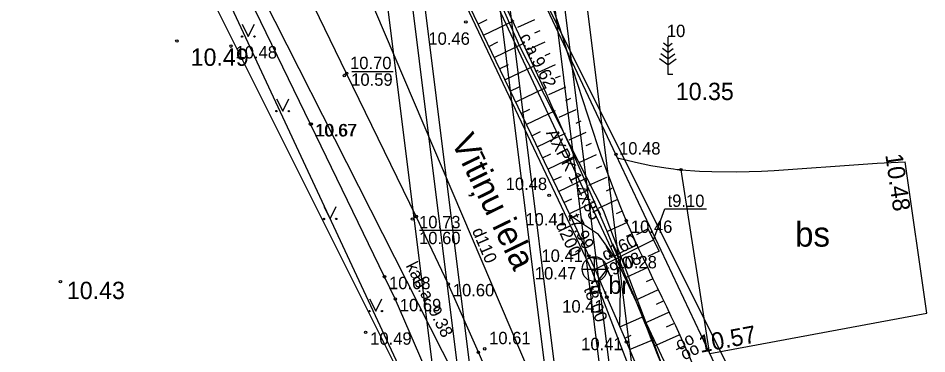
# Model space of a CAD drawing. Extents: x 502312.8 to 502402.4, y 308528.5 to 308602.
# Drawn here: x 502364.65 to 502401.34, y 308553.83 to 308567.38 of the extents above; entities that cross this region are included whole.
import ezdxf

# ---------------------------------------------------------------- set-up
doc = ezdxf.new("R2010")
doc.units = 0
for name, color, linetype in [('24', 7, 'Continuous'), ('APGR_SARK_####_####_#', 7, 'Continuous'), ('APGS_ACRL_####_####_#', 7, 'Continuous'), ('APGS_ACRL_####_TKST_#', 7, 'Continuous'), ('APGS_VADP_ZSPR_####_I', 7, 'Continuous'), ('APGS_VADP_ZSPR_TKST_I', 7, 'Continuous'), ('CELI_CAPM_####_####_#', 7, 'Continuous'), ('CELI_CMAL_####_####_#', 7, 'Continuous'), ('CELI_CSEG_####_TKST_#', 7, 'Continuous'), ('CELI_IELA_####_TKST_#', 7, 'Continuous'), ('ELEK_VADP_ZSPR_####_#', 7, 'Continuous'), ('ELEK_VADP_ZSPR_TKST_#', 7, 'Continuous'), ('ELEK_VADV_ASP1_####_#', 7, 'Continuous'), ('Level 51-1', 7, 'Continuous'), ('NORB_ZOGS_ZSTP_####_#', 7, 'Continuous'), ('RELJ_AATZ_####_TKST_#', 7, 'Continuous'), ('RELJ_ELEM_####_####_#', 7, 'Continuous'), ('RELJ_NOGA_####_####_#', 7, 'Continuous'), ('RELJ_NOGL_####_####_#', 7, 'Continuous'), ('SAKK_IZVK_####_TKST_#', 7, 'Continuous'), ('SAKK_KKAN_####_####_#', 7, 'Continuous'), ('SKAN_ELEM_####_####_#', 7, 'Continuous'), ('SKAN_ELEM_PAST_TKST_#', 7, 'Continuous'), ('SKAN_VADP_PAST_####_I', 7, 'Continuous'), ('SKAN_VADP_PAST_TKST_I', 7, 'Continuous'), ('TERT_DIAM_####_TKST_#', 7, 'Continuous'), ('TERT_ELEM_####_####_#', 7, 'Continuous'), ('TERT_KONT_####_####_#', 7, 'Continuous'), ('UDTK_VADP_UDEN_####_#', 7, 'Continuous'), ('UDTK_VADP_UDEN_TKST_#', 7, 'Continuous')]:
    doc.layers.add(name, color=color, linetype=linetype)

msp = doc.modelspace()

# ---------------------------------------------------------------- linework, layer by layer
at = {"layer": '24'}
for p, q in [((502364.984, 308585.593), (502381.693, 308549.732)), ((502394.734, 308550.484), (502382.191, 308575.562))]:
    msp.add_line(p, q, dxfattribs=at)
at = {"layer": 'APGR_SARK_####_####_#'}
for p, q in [((502382.191, 308575.562), (502394.734, 308550.484)), ((502369.848, 308573.413), (502381.693, 308549.732))]:
    msp.add_line(p, q, dxfattribs=at)
at = {"layer": 'APGS_ACRL_####_####_#'}
msp.add_lwpolyline([(502372.273, 308571.554), (502372.68, 308571.725), (502380.284, 308575.836), (502380.655, 308575.903), (502380.972, 308575.586), (502382.116, 308572.55), (502384.894, 308566.257), (502388.272, 308559.63), (502390.397, 308554.024), (502392.869, 308547.38), (502392.92, 308547.155)], dxfattribs=at)
at = {"layer": 'APGS_VADP_ZSPR_####_I'}
msp.add_lwpolyline([(502372.273, 308571.554), (502372.68, 308571.725), (502380.284, 308575.836), (502380.655, 308575.903), (502380.972, 308575.586), (502382.116, 308572.55), (502384.894, 308566.257), (502388.272, 308559.63), (502390.397, 308554.024), (502392.869, 308547.38), (502392.92, 308547.155)], dxfattribs=at)
at = {"layer": 'CELI_CAPM_####_####_#'}
for points in [[(502378.409, 308577.074), (502378.645, 308576.556), (502381.101, 308571.495), (502383.047, 308567.49), (502386.95, 308559.382), (502387.372, 308558.481), (502387.692, 308557.774), (502387.933, 308557.255), (502388.418, 308556.115), (502389.212, 308554.306), (502389.599, 308553.373), (502390.383, 308551.504), (502391.144, 308549.652), (502391.872, 308547.788), (502392.589, 308545.929), (502393.393, 308543.693), (502393.705, 308542.827)], [(502392.53, 308528.536), (502392.273, 308529.412), (502391.34, 308532.322), (502390.324, 308535.341), (502389.269, 308538.416), (502388.272, 308541.254), (502387.358, 308543.683), (502386.314, 308546.51), (502385.198, 308549.256), (502384.849, 308550.113), (502383.229, 308553.89), (502382.013, 308556.65), (502380.717, 308559.374), (502377.909, 308565.152), (502373.303, 308574.647)]]:
    msp.add_lwpolyline(points, dxfattribs=at)
at = {"layer": 'CELI_CMAL_####_####_#'}
for points in [[(502390.232, 308528.536), (502388.865, 308532.737), (502388.043, 308535.197), (502387.28, 308537.476), (502386.263, 308540.301), (502385.235, 308543.076), (502384.524, 308544.988), (502383.511, 308547.559), (502382.468, 308550.05), (502379.873, 308556.046), (502379.438, 308556.939), (502376.448, 308563.104), (502371.317, 308573.674)], [(502388.853, 308561.737), (502389.58, 308561.564), (502390.189, 308561.437), (502390.8, 308561.334), (502391.107, 308561.293), (502391.26, 308561.276), (502391.337, 308561.268), (502391.414, 308561.261), (502392.163, 308561.209), (502392.663, 308561.189), (502393.663, 308561.183), (502394.669, 308561.21), (502395.173, 308561.233), (502395.927, 308561.279), (502398.198, 308561.445), (502399.333, 308561.522), (502400.465, 308561.577)], [(502401.338, 308555.467), (502400.465, 308561.577)], [(502392.559, 308553.884), (502391.414, 308561.261)], [(502388.946, 308554.913), (502388.966, 308556.489), (502388.783, 308557.67), (502388.074, 308558.645), (502386.943, 308559.396)], [(502387.714, 308557.727), (502388.247, 308557.635), (502388.387, 308557.209), (502388.11, 308556.838)], [(502392.582, 308553.835), (502401.338, 308555.467)]]:
    msp.add_lwpolyline(points, dxfattribs=at)
at = {"layer": 'ELEK_VADP_ZSPR_####_#'}
msp.add_line((502372.196, 308572.819), (502383.39, 308550.751), dxfattribs=at)
at = {"layer": 'ELEK_VADV_ASP1_####_#'}
msp.add_line((502392.53, 308528.536), (502385.08, 308588.302), dxfattribs=at)
for points in [[(502389.003, 308528.536), (502381.58, 308588.091)], [(502389.406, 308528.536), (502381.98, 308588.115)], [(502391.22, 308528.536), (502383.78, 308588.224)], [(502391.623, 308528.536), (502384.18, 308588.248)], [(502384.469, 308528.536), (502377.051, 308588.051)], [(502385.476, 308528.536), (502378.08, 308587.88)], [(502385.98, 308528.536), (502378.58, 308587.91)]]:
    msp.add_lwpolyline(points, dxfattribs=at)
at = {"layer": 'Level 51-1'}
msp.add_line((502364.984, 308585.593), (502381.693, 308549.732), dxfattribs=at)
at = {"layer": 'NORB_ZOGS_ZSTP_####_#'}
msp.add_line((502388.785, 308561.881), (502380.198, 308580.055), dxfattribs=at)
msp.add_lwpolyline([(502394.21, 308550.464), (502393.13, 308552.674), (502388.785, 308561.881)], dxfattribs=at)
at = {"layer": 'RELJ_AATZ_####_TKST_#'}
for p, q in [((502378.121, 308565.226), (502379.789, 308565.226)), ((502380.859, 308558.821), (502382.526, 308558.821))]:
    msp.add_line(p, q, dxfattribs=at)
at = {"layer": 'RELJ_ELEM_####_####_#'}
for centre in [(502382.724, 308567.227), (502371.056, 308566.457), (502373.239, 308566.253), (502377.816, 308565.064), (502377.909, 308565.152), (502376.448, 308563.104), (502376.479, 308563.11), (502388.785, 308561.881), (502391.414, 308561.261), (502386.088, 308560.227), (502386.95, 308559.382), (502380.565, 308559.269), (502380.717, 308559.374), (502389.203, 308559.21), (502387.372, 308558.481), (502387.692, 308557.774), (502388.579, 308557.78), (502379.438, 308556.939), (502366.353, 308556.739), (502382.013, 308556.65), (502388.418, 308556.115), (502379.873, 308556.046), (502378.676, 308554.696), (502389.212, 308554.306), (502383.229, 308553.89), (502383.485, 308554.029)]:
    msp.add_circle(centre, 0.05, dxfattribs=at)
at = {"layer": 'RELJ_NOGA_####_####_#'}
for p, q in [((502383.214, 308567.143), (502383.587, 308567.322)), ((502383.431, 308566.692), (502384.67, 308567.289)), ((502385.499, 308567.32), (502384.804, 308567.003)), ((502385.706, 308566.865), (502385.499, 308566.771)), ((502383.648, 308566.242), (502384.018, 308566.42)), ((502385.914, 308566.41), (502385.228, 308566.097)), ((502383.865, 308565.791), (502385.095, 308566.383)), ((502386.121, 308565.955), (502385.916, 308565.862)), ((502384.082, 308565.341), (502384.449, 308565.517)), ((502384.299, 308564.89), (502385.516, 308565.476)), ((502386.329, 308565.501), (502385.648, 308565.19)), ((502386.537, 308565.046), (502386.332, 308564.953)), ((502384.515, 308564.44), (502384.878, 308564.614)), ((502386.744, 308564.591), (502386.063, 308564.28)), ((502384.732, 308563.989), (502385.933, 308564.567)), ((502386.952, 308564.136), (502386.747, 308564.043)), ((502384.949, 308563.538), (502385.306, 308563.71)), ((502385.166, 308563.088), (502386.346, 308563.656)), ((502387.159, 308563.681), (502386.475, 308563.369)), ((502387.367, 308563.226), (502387.16, 308563.132)), ((502385.383, 308562.637), (502385.733, 308562.806)), ((502385.6, 308562.187), (502386.754, 308562.743)), ((502387.574, 308562.771), (502386.881, 308562.455)), ((502387.782, 308562.317), (502387.572, 308562.221)), ((502385.817, 308561.736), (502386.159, 308561.901)), ((502386.034, 308561.286), (502387.157, 308561.827)), ((502387.99, 308561.862), (502387.282, 308561.538)), ((502388.198, 308561.407), (502387.983, 308561.309)), ((502386.25, 308560.835), (502386.582, 308560.995)), ((502386.467, 308560.385), (502387.554, 308560.908)), ((502388.406, 308560.952), (502387.678, 308560.619)), ((502388.614, 308560.498), (502388.391, 308560.396)), ((502386.684, 308559.934), (502387.004, 308560.088)), ((502386.901, 308559.484), (502387.945, 308559.986)), ((502388.822, 308560.043), (502388.066, 308559.697)), ((502389.03, 308559.588), (502388.798, 308559.482)), ((502389.238, 308559.134), (502388.448, 308558.772)), ((502389.446, 308558.679), (502389.203, 308558.568)), ((502389.655, 308558.225), (502388.822, 308557.843)), ((502389.863, 308557.77), (502389.606, 308557.652)), ((502390.071, 308557.316), (502389.192, 308556.912)), ((502390.28, 308556.861), (502390.009, 308556.737)), ((502390.488, 308556.406), (502389.561, 308555.981)), ((502390.696, 308555.952), (502390.411, 308555.821)), ((502390.905, 308555.497), (502389.93, 308555.05)), ((502388.942, 308554.92), (502389.827, 308555.309)), ((502391.113, 308555.043), (502390.813, 308554.906)), ((502389.143, 308554.462), (502389.404, 308554.577)), ((502389.338, 308554.002), (502390.203, 308554.361)), ((502391.321, 308554.588), (502390.299, 308554.12)), ((502391.53, 308554.134), (502391.216, 308553.99))]:
    msp.add_line(p, q, dxfattribs=at)
msp.add_spline([(502392.938, 308547.462), (502392.327, 308552.238), (502392.05, 308552.998), (502389.203, 308559.21), (502380.766, 308577.667), (502379.858, 308578.409), (502378.565, 308579.008)], degree=3, dxfattribs=at)
at = {"layer": 'RELJ_NOGL_####_####_#'}
msp.add_spline([(502392.938, 308547.462), (502388.885, 308557.685), (502380.794, 308575.385), (502379.35, 308578.02), (502378.565, 308579.008)], degree=3, dxfattribs=at)
at = {"layer": 'SAKK_KKAN_####_####_#'}
msp.add_lwpolyline([(502378.865, 308578.852), (502390.92, 308553.118), (502393.046, 308548.902)], dxfattribs=at)
at = {"layer": 'SKAN_ELEM_####_####_#'}
for p, q in [((502387.921, 308556.749), (502387.921, 308557.749)), ((502387.421, 308557.249), (502388.421, 308557.249))]:
    msp.add_line(p, q, dxfattribs=at)
msp.add_lwpolyline([(502389.629, 308558.65), (502390.076, 308558.874), (502390.524, 308557.98), (502390.077, 308557.756)], dxfattribs=at)
msp.add_circle((502387.921, 308557.249), 0.5, dxfattribs=at)
at = {"layer": 'SKAN_VADP_PAST_####_I'}
for points in [[(502373.002, 308587.759), (502378.517, 308576.782), (502387.809, 308557.18), (502392.481, 308545.051), (502396.902, 308528.536)], [(502387.809, 308557.18), (502390.3, 308558.427)]]:
    msp.add_lwpolyline(points, dxfattribs=at)
at = {"layer": 'SKAN_VADP_PAST_TKST_I'}
for p, q in [((502390.597, 308559.242), (502390.758, 308559.681)), ((502390.758, 308559.681), (502392.446, 308559.681)), ((502390.3, 308558.427), (502390.597, 308559.242))]:
    msp.add_line(p, q, dxfattribs=at)
at = {"layer": 'TERT_ELEM_####_####_#'}
for p, q in [((502373.688, 308567.137), (502373.938, 308566.637)), ((502373.938, 308566.637), (502374.188, 308567.137)), ((502390.881, 308566.618), (502390.881, 308565.118)), ((502390.881, 308565.992), (502390.665, 308566.15)), ((502390.881, 308566.242), (502390.705, 308566.37)), ((502390.881, 308566.242), (502391.055, 308566.37)), ((502390.881, 308565.992), (502391.097, 308566.15)), ((502390.881, 308565.492), (502390.549, 308565.736)), ((502390.881, 308565.742), (502390.603, 308565.946)), ((502390.881, 308565.742), (502391.159, 308565.946)), ((502390.881, 308565.492), (502391.215, 308565.736)), ((502390.881, 308565.118), (502391.081, 308565.118)), ((502375.077, 308564.131), (502375.327, 308563.631)), ((502375.327, 308563.631), (502375.577, 308564.131)), ((502376.993, 308559.773), (502377.243, 308559.273)), ((502377.243, 308559.273), (502377.493, 308559.773)), ((502378.833, 308556.054), (502379.083, 308555.554)), ((502379.083, 308555.554), (502379.333, 308556.054))]:
    msp.add_line(p, q, dxfattribs=at)
for centre, radius in [((502373.688, 308566.636), 0.028), ((502374.188, 308566.636), 0.0263), ((502375.077, 308563.631), 0.028), ((502375.577, 308563.631), 0.0263), ((502376.993, 308559.273), 0.028), ((502377.493, 308559.273), 0.0263), ((502378.833, 308555.553), 0.028), ((502379.333, 308555.553), 0.0263)]:
    msp.add_circle(centre, radius, dxfattribs=at)
at = {"layer": 'TERT_KONT_####_####_#'}
msp.add_spline([(502368.421, 308580.073), (502364.888, 308583.145), (502359.074, 308582.726), (502336.999, 308579.84), (502335.385, 308579.318), (502336.097, 308569.387), (502336.741, 308557.487), (502335.314, 308546.766)], degree=3, dxfattribs=at)
at = {"layer": 'UDTK_VADP_UDEN_####_#'}
msp.add_line((502387.742, 308547.347), (502379.047, 308567.724), dxfattribs=at)

# ---------------------------------------------------------------- texts
at = {"layer": 'APGS_ACRL_####_TKST_#'}
msp.add_text('c.a.9.62', height=0.5, rotation=297.0094, dxfattribs=at).set_placement((502384.877, 308566.62))
at = {"layer": 'APGS_VADP_ZSPR_TKST_I'}
msp.add_text('AXPK 1-4x35', height=0.5, rotation=297.0094, dxfattribs=at).set_placement((502385.951, 308562.751))
at = {"layer": 'CELI_CSEG_####_TKST_#'}
for s, height, p in [('bs', 1, (502396.017, 308558.158)), ('a.br.', 0.7, (502387.705, 308556.248))]:
    msp.add_text(s, height=height, dxfattribs=at).set_placement(p)
at = {"layer": 'CELI_IELA_####_TKST_#'}
msp.add_text('Vītiņu iela', height=1, rotation=295.9189, dxfattribs=at).set_placement((502382.11, 308562.41))
at = {"layer": 'ELEK_VADP_ZSPR_TKST_#'}
msp.add_text('kab.a. 9.38', height=0.5, rotation=296.8963, dxfattribs=at).set_placement((502380.289, 308557.389))
at = {"layer": 'RELJ_AATZ_####_TKST_#'}
for s, height, p in [(' 10.46', 0.5, (502381.026, 308566.307)), ('10.49', 0.7, (502371.612, 308565.457)), (' 10.48', 0.5, (502373.239, 308565.753)), (' 10.70', 0.5, (502377.863, 308565.323)), (' 10.59', 0.5, (502377.909, 308564.652)), (' 10.35', 0.7, (502390.941, 308564.074)), (' 10.67', 0.5, (502376.448, 308562.604)), (' 10.67', 0.5, (502376.479, 308562.61)), (' 10.48', 0.5, (502388.725, 308561.876)), (' 10.48', 0.5, (502384.148, 308560.442)), (' 10.41', 0.5, (502384.942, 308559.01)), (' 10.73', 0.5, (502380.65, 308558.897)), (' 10.46', 0.5, (502389.203, 308558.71)), (' 10.60', 0.5, (502380.649, 308558.257)), (' 10.41', 0.5, (502385.591, 308557.541)), (' 10.28', 0.5, (502388.579, 308557.28)), (' 10.68', 0.5, (502379.438, 308556.439)), (' 10.43', 0.7, (502366.353, 308556.039)), (' 10.60', 0.5, (502382.013, 308556.15)), (' 10.69', 0.5, (502379.873, 308555.546)), (' 10.41', 0.5, (502386.43, 308555.496)), (' 10.49', 0.5, (502378.676, 308554.196)), (' 10.61', 0.5, (502383.478, 308554.217)), (' 10.41', 0.5, (502387.195, 308553.976))]:
    msp.add_text(s, height=height, dxfattribs=at).set_placement(p)
for s, rotation, p in [(' 10.48', 278.1301, (502399.623, 308562.124)), (' 10.57', 10.5601, (502391.936, 308553.818))]:
    msp.add_text(s, height=0.7, rotation=rotation, dxfattribs=at).set_placement(p)
at = {"layer": 'SAKK_IZVK_####_TKST_#'}
for p in [(502391.339, 308553.952), (502391.54, 308553.554)]:
    msp.add_text('oo', height=0.5, rotation=26.757, dxfattribs=at).set_placement(p)
at = {"layer": 'SKAN_ELEM_PAST_TKST_#'}
msp.add_text(' 10.47', height=0.5, dxfattribs=at).set_placement((502385.325, 308556.831))
at = {"layer": 'SKAN_VADP_PAST_TKST_I'}
for s, rotation, p in [('t9.10', 359.6331, (502390.87, 308559.764)), ('t7.99', 295.3625, (502386.844, 308559.341)), ('d200', 295.3625, (502386.336, 308559.039)), ('d160', 26.5926, (502388.363, 308557.569)), ('t9.08', 24.083, (502388.495, 308556.905)), ('t8.00', 290.624, (502387.472, 308556.452))]:
    msp.add_text(s, height=0.5, rotation=rotation, dxfattribs=at).set_placement(p)
at = {"layer": 'TERT_DIAM_####_TKST_#'}
msp.add_text(' 10', height=0.5, dxfattribs=at).set_placement((502390.656, 308566.618))
at = {"layer": 'UDTK_VADP_UDEN_TKST_#'}
msp.add_text('d110', height=0.5, rotation=293.1088, dxfattribs=at).set_placement((502382.963, 308558.802))

doc.saveas('drawing.dxf')
